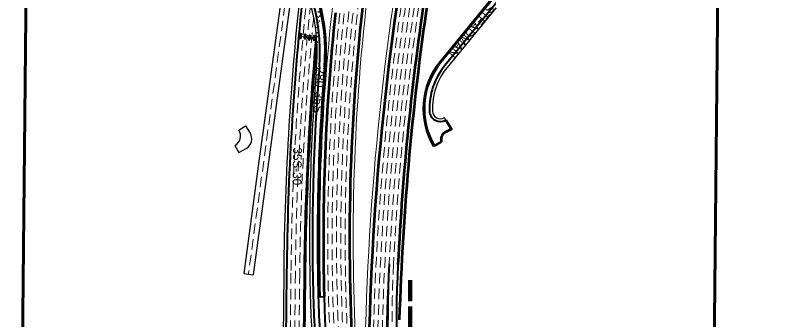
# Model space of a CAD drawing. Extents: x 2329387 to 2347382, y 6951580 to 6987999.
# Drawn here: x 2330661 to 2332753, y 6959510 to 6960345 of the extents above; entities that cross this region are included whole.
import ezdxf

# ---------------------------------------------------------------- set-up
doc = ezdxf.new("R2010")
doc.units = 0
doc.header["$LTSCALE"] = 9.6
for name, pattern in [('DOTTED', [1.5, 0.3, -1.2]), ('LONG_DASHED', [7.5, 6, -1.5]), ('MEDIUM_DASHED', [4.5, 3, -1.5])]:
    doc.linetypes.add(name, pattern=pattern)
for name, color, linetype, lineweight in [('26', 7, 'Continuous', 53), ('27', 7, 'Continuous', 40), ('41', 7, 'Continuous', 35), ('50', 7, 'MEDIUM_DASHED', 13), ('59', 7, 'LONG_DASHED', 90), ('62', 7, 'Continuous', 60), ('63', 7, 'Continuous', 25)]:
    doc.layers.add(name, color=color, linetype=linetype, lineweight=lineweight)
doc.layers.add('40', color=7, linetype='Continuous')

msp = doc.modelspace()

# ---------------------------------------------------------------- linework, layer by layer
at = {"layer": '26', "lineweight": 13}
for centre, radius, start, end in [((2337309.03, 6959730.876), 5811.578, 172.80217, 181.55357), ((2337309.03, 6959730.876), 5719.578, 173.00338, 183.29735), ((2339270.111, 6959279.267), 7649.437, 171.46588, 181.61718)]:
    msp.add_arc(centre, radius, start, end, dxfattribs=at)
at = {"layer": '26'}
for centre, radius, start, end in [((2337309.03, 6959730.876), 5729.578, 172.98959, 183.29735), ((2339270.111, 6959279.267), 7639.437, 171.46189, 181.6147), ((2339270.111, 6959279.267), 7567.437, 171.38894, 177.10146), ((2339270.111, 6959279.267), 7557.437, 171.37243, 178.25098), ((2337309.03, 6959730.876), 5801.578, 173.85545, 181.55357)]:
    msp.add_arc(centre, radius, start, end, dxfattribs=at)
at = {"layer": '27'}
for p, q in [((2332116.511, 6960564.941), (2331830.32, 6960215.843)), ((2332103.417, 6960526.886), (2331841.147, 6960206.967)), ((2331406.561, 6959637.995), (2331401.059, 6959098.144)), ((2331454.558, 6959637.506), (2331449.057, 6959097.655)), ((2331493.59, 6959573.153), (2331509.584, 6959573.586))]:
    msp.add_line(p, q, dxfattribs=at)
at = {"layer": '27', "lineweight": 25}
for p, q in [((2332109.524, 6960521.717), (2331847.333, 6960201.895)), ((2332050.366, 6960490.566), (2331827.226, 6960218.379)), ((2331844.164, 6960057.424), (2331840.145, 6960064.341)), ((2331812.81, 6959987.287), (2331809.367, 6959985.252)), ((2331398.561, 6959638.076), (2331393.06, 6959098.226)), ((2331458.558, 6959637.465), (2331453.056, 6959097.614))]:
    msp.add_line(p, q, dxfattribs=at)
at = {"layer": '27', "lineweight": 53}
msp.add_line((2331812.81, 6959987.287), (2331832.512, 6959997.839), dxfattribs=at)
msp.add_lwpolyline([(2331844.164, 6960057.424), (2331859.152, 6960032.891), (2331841.44, 6960023.431)], dxfattribs=at)
at = {"layer": '27'}
for centre, radius, start, end in [((2339406.145, 6959556.474), 7976, 170.51466, 170.51466), ((2330989.258, 6960244.547), 509.035, 355.35626, 41.62086), ((2330989.258, 6960244.547), 523.035, 355.35626, 38.15909), ((2339406.145, 6959556.474), 8000, 173.72103, 179.41614), ((2339406.145, 6959556.474), 7952, 174.70032, 179.41614), ((2337315.279, 6959730.707), 5837.82, 175.35626, 181.55024), ((2337315.279, 6959730.707), 5823.82, 175.35626, 181.55024), ((2331984.988, 6960089.045), 200, 140.65505, 210.58328), ((2331984.988, 6960089.045), 186, 140.65505, 182.08749), ((2331829.092, 6960083.363), 30, 182.08749, 300.15936), ((2339270.111, 6959279.267), 7591.437, 177.10146, 180.92442), ((2334982.211, 6959496.373), 3298.045, 177.10146, 186.58309), ((2334982.211, 6959496.373), 3274.045, 177.10146, 186.58309), ((2334468.92, 6959653.675), 2990.419, 181.55024, 185.58802), ((2334468.92, 6959653.675), 2976.419, 181.55024, 185.58802), ((2337309.03, 6959730.876), 5801.578, 181.55357, 183.29735)]:
    msp.add_arc(centre, radius, start, end, dxfattribs=at)
at = {"layer": '27', "lineweight": 25}
for centre, radius, start, end in [((2330989.258, 6960244.547), 501.035, 355.35626, 41.62086), ((2330989.258, 6960244.547), 527.035, 355.35626, 30.28163), ((2339406.145, 6959556.474), 8008, 173.61844, 179.41614), ((2339406.145, 6959556.474), 7948, 174.88074, 179.41614), ((2331984.988, 6960089.045), 204, 140.65505, 210.58327), ((2337315.279, 6959730.707), 5845.82, 175.35626, 181.55024), ((2337315.279, 6959730.707), 5819.82, 175.35626, 181.55024), ((2331984.988, 6960089.045), 178, 140.65505, 182.08749), ((2331829.092, 6960083.363), 22, 182.08749, 300.15936), ((2334468.92, 6959653.675), 2998.419, 181.55024, 185.58802)]:
    msp.add_arc(centre, radius, start, end, dxfattribs=at)
at = {"layer": '27', "linetype": 'DOTTED'}
msp.add_arc((2339406.145, 6959556.474), 7952, 174.02309, 174.70032, dxfattribs=at)
at = {"layer": '27', "linetype": 'DOTTED', "lineweight": 25}
msp.add_arc((2339406.145, 6959556.474), 7948, 174.09944, 174.88074, dxfattribs=at)
at = {"layer": '27', "lineweight": 53}
msp.add_arc((2331850.863, 6960005.79), 20, 118.10939, 203.4242, dxfattribs=at)
at = {"layer": '41'}
for points in [[(2331447.248, 6960294.667), (2331444.262, 6960294.956), (2331443.605, 6960288.181), (2331441.179, 6960288.416), (2331444.245, 6960280.885), (2331448.701, 6960287.687), (2331446.592, 6960287.892)], [(2331459.767, 6960293.497), (2331456.781, 6960293.786), (2331456.124, 6960287.011), (2331453.698, 6960287.246), (2331456.764, 6960279.715), (2331461.22, 6960286.517), (2331459.111, 6960286.722)], [(2331471.518, 6960290.649), (2331468.532, 6960290.938), (2331467.875, 6960284.163), (2331465.449, 6960284.399), (2331468.516, 6960276.867), (2331472.971, 6960283.669), (2331470.862, 6960283.874)], [(2331484.037, 6960289.479), (2331481.051, 6960289.768), (2331480.394, 6960282.993), (2331477.968, 6960283.228), (2331481.035, 6960275.697), (2331485.49, 6960282.499), (2331483.381, 6960282.704)]]:
    msp.add_lwpolyline(points, close=True, dxfattribs=at)
at = {"layer": '50'}
for p, q in [((2331418.56, 6959637.873), (2331413.058, 6959098.022)), ((2331430.559, 6959637.75), (2331425.058, 6959097.9)), ((2331442.559, 6959637.628), (2331437.057, 6959097.777))]:
    msp.add_line(p, q, dxfattribs=at)
for centre, radius, start, end in [((2337309.03, 6959730.876), 5765.578, 172.92379, 183.29735), ((2337309.03, 6959730.876), 5753.578, 172.94854, 183.29735), ((2337309.03, 6959730.876), 5741.578, 172.97047, 183.29735), ((2339406.145, 6959556.474), 7988, 173.8931, 179.41614), ((2339270.111, 6959279.267), 7627.437, 171.45517, 181.61172), ((2339270.111, 6959279.267), 7615.437, 171.44631, 181.60872), ((2339270.111, 6959279.267), 7603.437, 171.43529, 181.60572), ((2339270.111, 6959279.267), 7591.437, 171.42207, 177.10146), ((2339270.111, 6959279.267), 7579.437, 171.40663, 177.10146), ((2339406.145, 6959556.474), 7976, 174.09518, 179.41614), ((2337309.03, 6959730.876), 5789.578, 173.85545, 183.29735), ((2337309.03, 6959730.876), 5777.578, 173.85545, 183.29735), ((2339406.145, 6959556.474), 7964, 174.34568, 179.41614), ((2334982.211, 6959496.373), 3286.045, 177.10146, 186.58309)]:
    msp.add_arc(centre, radius, start, end, dxfattribs=at)
at = {"layer": '59'}
msp.add_lwpolyline([(2331746, 6959618.5), (2331746, 6959343.5), (2331793.053, 6959077.812)], dxfattribs=at)
at = {"layer": '62'}
msp.add_lwpolyline([(2332642.295, 6965522.154), (2332560.849, 6957416.973), (2330660.943, 6957436.065), (2330739.467, 6965250.394)], close=True, dxfattribs=at)
at = {"layer": '63', "linetype": 'MEDIUM_DASHED', "lineweight": 13}
msp.add_line((2331419.434, 6960501.422), (2331301.557, 6959634.781), dxfattribs=at)
at = {"layer": '63'}
for p, q in [((2331430.021, 6960482.799), (2331314.438, 6959633.029)), ((2331275.332, 6960029.964), (2331293.968, 6960041.656)), ((2331293.968, 6960041.656), (2331306.24, 6960022.097)), ((2331264.618, 6959987.866), (2331275.396, 6959968.687)), ((2331275.396, 6959968.687), (2331295.525, 6959979.999)), ((2331332.504, 6959958.761), (2331288.676, 6959636.534)), ((2331288.676, 6959636.534), (2331314.438, 6959633.029))]:
    msp.add_line(p, q, dxfattribs=at)
msp.add_lwpolyline([(2331408.66, 6960518.661), (2331342.19, 6960029.976), (2331332.504, 6959958.761)], dxfattribs=at)
for centre in [(2331249.92, 6960014.019), (2331280.828, 6960006.152)]:
    msp.add_arc(centre, 30, 299.33449, 32.10577, dxfattribs=at)

# ---------------------------------------------------------------- texts
at = {"layer": '40'}
for s, rotation, p in [('STEADMAN', 230.757, (2331961.07, 6960379.281)), ('35S-30', 268.862, (2331424.636, 6959982.779))]:
    msp.add_text(s, height=24, rotation=rotation, dxfattribs=at).set_placement(p)
at = {"layer": '40', "width": 1.05}
msp.add_text('280-35S', height=24, rotation=266.425, dxfattribs=at).set_placement((2331488.648, 6960203.984))

doc.saveas('drawing.dxf')
